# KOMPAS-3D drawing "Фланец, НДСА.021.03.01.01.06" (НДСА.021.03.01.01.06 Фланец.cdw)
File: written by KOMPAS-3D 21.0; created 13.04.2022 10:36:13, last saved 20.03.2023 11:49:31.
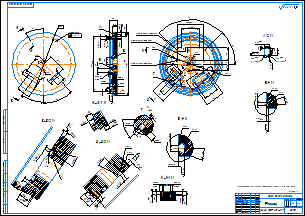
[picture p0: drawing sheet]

Sheet 1: A1, landscape

Document properties: PLM_CDWXDTO: <item xmlns="http://appius.ru/pdm" xmlns:xs="http://www.w3.org/2001/XMLSchema" xmlns:xsi="http://www.w3.org/2001/XMLSchema-instance" xsi:type="item">  <element xmlns:d2p1="http://v8.1c.ru/8.1/data/enterprise/current-config" xsi:type="d2p1:CatalogRef.aps_Элемен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; Масса: 6.75238; Знак неуказанной шероховатости: 4; Параметр неуказанной шероховатости: Ra 6,3; 209661138342: <item xmlns="http://appius.ru/pdm" xmlns:xs="http://www.w3.org/2001/XMLSchema" xmlns:xsi="http://www.w3.org/2001/XMLSchema-instance" xsi:type="item">  <element xmlns:d2p1="http://v8.1c.ru/8.1/data/enterprise/current-config" xsi:type="d2p1:CatalogRef.aps_Элемен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; 209661138442: <item xmlns="http://appius.ru/pdm" xmlns:xs="http://www.w3.org/2001/XMLSchema" xmlns:xsi="http://www.w3.org/2001/XMLSchema-instance" xsi:type="item">  <element xmlns:d2p1="http://v8.1c.ru/8.1/data/enterprise/current-config" xsi:type="d2p1:CatalogRef.aps_Элемен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; 387070304793: <item xmlns="http://appius.ru/pdm" xmlns:xs="http://www.w3.org/2001/XMLSchema" xmlns:xsi="http://www.w3.org/2001/XMLSchema-instance" xsi:type="item">  <element xmlns:d2p1="http://v8.1c.ru/8.1/data/enterprise/current-config" xsi:type="d2p1:CatalogRef.aps_Элемен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; 387070304893: <item xmlns="http://appius.ru/pdm" xmlns:xs="http://www.w3.org/2001/XMLSchema" xmlns:xsi="http://www.w3.org/2001/XMLSchema-instance" xsi:type="item">  <element xmlns:d2p1="http://v8.1c.ru/8.1/data/enterprise/current-config" xsi:type="d2p1:CatalogRef.aps_Элемен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; PDM_DOCXDTO: <item xmlns="http://appius.ru/pdm" xmlns:xs="http://www.w3.org/2001/XMLSchema" xmlns:xsi="http://www.w3.org/2001/XMLSchema-instance" xsi:type="item">  <element xmlns:d2p1="http://v8.1c.ru/8.1/data/enterprise/current-config" xsi:type="d2p1:CatalogRef.aps_Элемен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; PDM_ITEMXDTO: <item xmlns="http://appius.ru/pdm" xmlns:xs="http://www.w3.org/2001/XMLSchema" xmlns:xsi="http://www.w3.org/2001/XMLSchema-instance" xsi:type="item">  <element xmlns:d2p1="http://v8.1c.ru/8.1/data/enterprise/current-config" xsi:type="d2p1:CatalogRef.aps_Элемен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; PDM_DRAWINGXDTO: <item xmlns="http://appius.ru/pdm" xmlns:xs="http://www.w3.org/2001/XMLSchema" xmlns:xsi="http://www.w3.org/2001/XMLSchema-instance" xsi:type="item">  <element xmlns:d2p1="http://v8.1c.ru/8.1/data/enterprise/current-config" xsi:type="d2p1:CatalogRef.aps_Элемен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; Полное имя файла: НДСА.021.03.01.01.06 Фланец.m3d; Автор: 111

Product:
- Part/product: Фланец  | designation НДСА.021.03.01.01.06
    Материал: АМг2,5 ГОСТ 4784-97 (density 2680 kg/m3)
    Масса: 6.75238
    additional columns: <item xmlns="http://appius.ru/pdm" xmlns:xs="http://www.w3.org/2001/XMLSchema" x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; <item xmlns="http://appius.ru/pdm" xmlns:xs="http://www.w3.org/2001/XMLSchema" x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; <item xmlns="http://appius.ru/pdm" xmlns:xs="http://www.w3.org/2001/XMLSchema" x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; <item xmlns="http://appius.ru/pdm" xmlns:xs="http://www.w3.org/2001/XMLSchema" x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; <item xmlns="http://appius.ru/pdm" xmlns:xs="http://www.w3.org/2001/XMLSchema" x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; <item xmlns="http://appius.ru/pdm" xmlns:xs="http://www.w3.org/2001/XMLSchema" x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; <item xmlns="http://appius.ru/pdm" xmlns:xs="http://www.w3.org/2001/XMLSchema" x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
    source file: НДСА.021.03.01.01.06 Фланец.cdw

Title block, sheet 1: Наименование: Фланец; designation: НДСА.021.03.01.01.06; Материал: АМг2,5 ГОСТ 4784-97; Масса: 6,75; Количество листов документа: 1; organisation: ЭСТО; Форматы листов документа: A1; stored path: C:\Users\s.pischagina\Desktop\PLM\НДСА.021.03.01.01.06 Фланец.cdw; Разработал: Пищагина; Проверил: Белецкий; Утвердил: Виноградов; Разработал, date: 15.04.22

Views: Вид 1, Вид:1, Проекционный вид 2, Местный разрез 1, Проекционный вид 3, Выносной элемент 4, Выносной элемент 5, Выносной элемент 6, Разрез Г-Г, Разрез Д-Д, Разрез Е-Е, Разрез Ж-Ж, Выносной элемент 11, Выносной элемент А, Выносной элемент, Выносной элемент Б, Выносной элемент В, Разрез И-И, Выносной элемент Г
Referenced files in C:\Users\s.pischagina\Desktop\PLM\: НДСА.021.03.01.01.06 Фланец.m3d
Referenced files in C:\Users\korychko\Desktop\PLM\: НДСА.021.03.01.01.06 Фланец.m3d
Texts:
  Ra 1,6
  Ревизия 1
  Ra 6,3
  Ra 6,3 ( )
  Корячко
  НДСА.021.03.01.01.06 Фланец
Dimensions and other numbers on the sheet: 96; 94,8; 300; -7Н; 6отв; 5; 30; 70; 17; 47; 6; 24; 12; 7; 25; 350; 18±0,1; 35; 4; 3отв; 14; 22; 43; 1; 2; 8; 12 отв.; 5,5; 306; 11±0,1; 10±0,1; 36; 75; 23; 100±0,1; 146±0,07; 112; 60; 62; 83; 107; 57; 80; 15; 4отв М4-7Нх(15 0.5)-17; 2отв М6-7Нх(12 0.5)-14; 2отв М4-7Нх(8 0.5)-10; 290; 9,6; 5,75; 0,8; 2 радиуса; 0,2; 1,6±0,05; 1,32; 0,4; 0,13; 4,32±0,05; 4,57; 0,79; 0,38; 4отв; 3; 2отв; 13; 0,5; 1:2; 6,75; 15.04.22; 06.03.2023; 1233

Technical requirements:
  Неуказанные предельные отклонения размеров: H12, h12, JS12.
